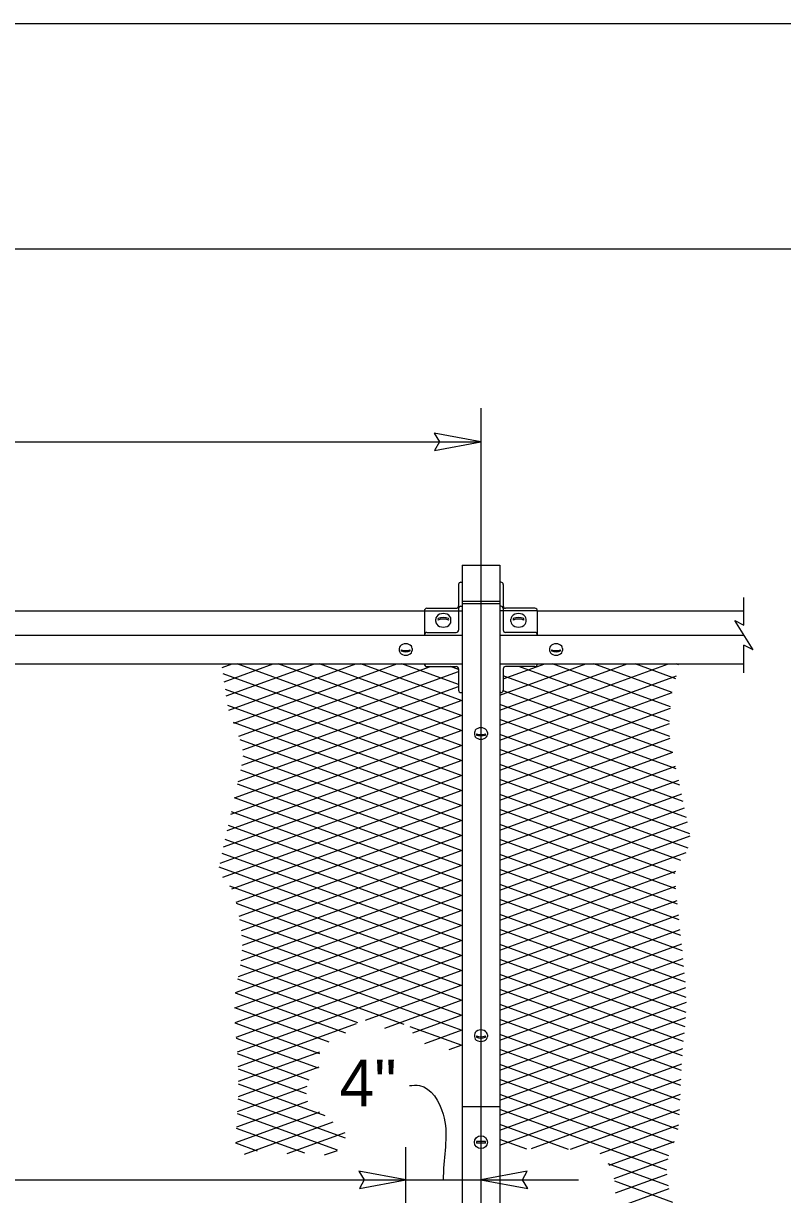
# Model space of a CAD drawing. Extents: x 0 to 2.83, y -0.03 to 1.83.
# Drawn here: x 0.4839 to 0.6943, y 1.5086 to 1.8333 of the extents above; entities that cross this region are included whole.
import ezdxf

# ---------------------------------------------------------------- set-up
doc = ezdxf.new("R2010")
doc.units = 0
for name, color, linetype in [('52', 7, 'Continuous'), ('54', 7, 'Continuous'), ('55', 7, 'Continuous'), ('56', 7, 'Continuous'), ('57', 7, 'Continuous'), ('63', 7, 'Continuous')]:
    doc.layers.add(name, color=color, linetype=linetype)

msp = doc.modelspace()

# ---------------------------------------------------------------- linework, layer by layer
at = {"layer": '52'}
for p, q in [((0.6054476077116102, 1.6831667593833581), (0.6158642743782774, 1.6831667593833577)), ((0.6054476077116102, 1.6831667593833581), (0.6054476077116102, 1.6707794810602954)), ((0.6158642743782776, 1.6831667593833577), (0.6158642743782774, 1.6707794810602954)), ((0.6044710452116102, 1.6777778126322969), (0.6044710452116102, 1.665152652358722)), ((0.6051220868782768, 1.6784288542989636), (0.6054476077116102, 1.6784288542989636)), ((0.6161897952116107, 1.6784288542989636), (0.6158642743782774, 1.6784288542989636)), ((0.6168408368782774, 1.6777778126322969), (0.6168408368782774, 1.665152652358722)), ((0.6054476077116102, 1.6731232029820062), (0.6158642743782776, 1.6731232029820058)), ((0.6158642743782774, 1.6723751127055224), (0.6054476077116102, 1.6723751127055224)), ((0.2096142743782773, 1.670449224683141), (0.6054476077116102, 1.670449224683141)), ((0.5950309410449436, 1.670546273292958), (0.5950309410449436, 1.6637535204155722)), ((0.5950309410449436, 1.670449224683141), (0.6054476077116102, 1.670449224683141)), ((0.5956819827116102, 1.6711973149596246), (0.6038200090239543, 1.6711973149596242)), ((0.6051220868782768, 1.6717331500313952), (0.6054476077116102, 1.6717331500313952)), ((0.6054476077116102, 1.6707794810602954), (0.6054476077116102, 1.5329433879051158)), ((0.6161897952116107, 1.6717331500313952), (0.6158642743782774, 1.6717331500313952)), ((0.6158642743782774, 1.6707794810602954), (0.6158642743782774, 1.5329433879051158)), ((0.626280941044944, 1.670449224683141), (0.6158642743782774, 1.670449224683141)), ((0.6256298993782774, 1.6711973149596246), (0.6174918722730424, 1.6711973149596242)), ((0.626280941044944, 1.670546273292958), (0.626280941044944, 1.6637535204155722)), ((0.626280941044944, 1.670449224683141), (0.68357260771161, 1.670449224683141)), ((0.5981233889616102, 1.6675598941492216), (0.59812338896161, 1.6681390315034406)), ((0.6023551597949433, 1.6675598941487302), (0.6023551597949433, 1.6681390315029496)), ((0.618956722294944, 1.6675598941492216), (0.6189567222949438, 1.6681390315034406)), ((0.6231884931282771, 1.6675598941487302), (0.6231884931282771, 1.6681390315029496)), ((0.1991976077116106, 1.6637535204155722), (0.6054476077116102, 1.6637535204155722)), ((0.5956819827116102, 1.6645016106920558), (0.6038200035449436, 1.6645016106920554)), ((0.6158642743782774, 1.6637535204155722), (0.68357260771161, 1.6637535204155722)), ((0.6256298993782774, 1.6645016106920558), (0.617491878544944, 1.6645016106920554)), ((0.5880322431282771, 1.6600087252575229), (0.5880322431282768, 1.659518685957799)), ((0.5916129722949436, 1.660008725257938), (0.5916129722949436, 1.6595186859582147)), ((0.629698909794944, 1.660008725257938), (0.629698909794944, 1.6595186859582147)), ((0.6332796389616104, 1.6600087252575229), (0.6332796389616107, 1.659518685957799)), ((0.1991976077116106, 1.6557738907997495), (0.6054476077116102, 1.6557738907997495)), ((0.5950309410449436, 1.6557628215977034), (0.5950309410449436, 1.6556768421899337)), ((0.5956819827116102, 1.655025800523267), (0.6038200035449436, 1.655025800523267)), ((0.6044710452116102, 1.6543747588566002), (0.6044710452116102, 1.6484453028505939)), ((0.6158642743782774, 1.6557738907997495), (0.68357260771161, 1.6557738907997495)), ((0.6168408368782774, 1.6543747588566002), (0.6168408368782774, 1.6484453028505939)), ((0.6256298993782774, 1.655025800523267), (0.617491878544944, 1.655025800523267)), ((0.626280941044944, 1.6557628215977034), (0.626280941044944, 1.6556768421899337)), ((0.6051220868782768, 1.6477942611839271), (0.6054476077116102, 1.6477942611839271)), ((0.6161897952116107, 1.6477942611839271), (0.6158642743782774, 1.6477942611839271)), ((0.6088655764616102, 1.636711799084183), (0.6088655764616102, 1.6362217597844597)), ((0.6124463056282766, 1.6367117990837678), (0.6124463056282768, 1.636221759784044)), ((0.6088655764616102, 1.552925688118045), (0.6088655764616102, 1.552435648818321)), ((0.6124463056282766, 1.5529256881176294), (0.6124463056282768, 1.552435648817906)), ((0.6054476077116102, 1.5330983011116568), (0.6158642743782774, 1.5330983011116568)), ((0.6054476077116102, 1.5329433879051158), (0.6054476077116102, 1.1621577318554)), ((0.6158642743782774, 1.5329433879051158), (0.6158642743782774, 1.1621577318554)), ((0.611902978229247, 1.5233909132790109), (0.6094089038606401, 1.5233909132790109)), ((0.611902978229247, 1.5229297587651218), (0.6094089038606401, 1.5229297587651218))]:
    msp.add_line(p, q, dxfattribs=at)
msp.add_circle((0.6106559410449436, 1.5231603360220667), 0.0017903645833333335, dxfattribs=at)
for centre, radius, start, end in [((0.6051220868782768, 1.6777778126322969), 0.0006510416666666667, 90, 180), ((0.6161897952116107, 1.6777778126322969), 0.0006510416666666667, 7.0164775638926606e-15, 90), ((0.5956819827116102, 1.670546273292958), 0.0006510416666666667, 90.00000000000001, 188.57284229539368), ((0.6038200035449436, 1.6718483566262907), 0.0006510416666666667, 270, 0), ((0.6051220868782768, 1.6710821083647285), 0.0006510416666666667, 90, 180), ((0.6161897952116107, 1.6710821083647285), 0.0006510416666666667, 7.0164775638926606e-15, 90), ((0.617491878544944, 1.6718483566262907), 0.0006510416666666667, 180, 270), ((0.6256298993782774, 1.670546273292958), 0.0006510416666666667, 351.4271577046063, 90), ((0.6002392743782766, 1.6645999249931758), 0.004024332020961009, 68.51761783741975, 111.48238216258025), ((0.6002392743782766, 1.66418861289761), 0.004024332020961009, 68.51761783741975, 111.48238216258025), ((0.6210726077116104, 1.6645999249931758), 0.004024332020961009, 68.51761783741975, 111.48238216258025), ((0.6210726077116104, 1.66418861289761), 0.004024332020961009, 68.51761783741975, 111.48238216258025), ((0.5956819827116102, 1.663850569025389), 0.0006510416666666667, 90.00000000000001, 188.57284229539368), ((0.6038200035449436, 1.665152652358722), 0.0006510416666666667, 270, 0), ((0.617491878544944, 1.665152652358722), 0.0006510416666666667, 180, 270), ((0.6256298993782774, 1.663850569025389), 0.0006510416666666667, 351.4271577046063, 90), ((0.5898226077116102, 1.66286134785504), 0.003405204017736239, 248.51761783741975, 291.4823821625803), ((0.5898226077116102, 1.6625133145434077), 0.003405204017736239, 248.51761783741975, 291.4823821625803), ((0.6314892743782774, 1.66286134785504), 0.003405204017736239, 248.51761783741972, 291.4823821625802), ((0.6314892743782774, 1.6625133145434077), 0.003405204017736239, 248.51761783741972, 291.4823821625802), ((0.5956819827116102, 1.6556768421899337), 0.0006510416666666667, 171.42715770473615, 270), ((0.6038200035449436, 1.6543747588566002), 0.0006510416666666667, 0, 89.99999999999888), ((0.617491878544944, 1.6543747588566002), 0.0006510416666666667, 90.00000000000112, 180), ((0.6256298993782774, 1.6556768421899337), 0.0006510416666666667, 270, 8.572842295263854), ((0.6051220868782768, 1.6484453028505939), 0.0006510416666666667, 180, 270), ((0.6161897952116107, 1.6484453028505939), 0.0006510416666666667, 270, 360), ((0.6106559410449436, 1.639564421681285), 0.003405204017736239, 248.51761783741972, 291.4823821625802), ((0.6106559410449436, 1.6392163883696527), 0.003405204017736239, 248.51761783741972, 291.4823821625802), ((0.6106559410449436, 1.5557783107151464), 0.003405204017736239, 248.51761783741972, 291.4823821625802), ((0.6106559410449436, 1.5554302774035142), 0.003405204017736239, 248.51761783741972, 291.4823821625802), ((0.6106559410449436, 1.5231603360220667), 0.0012681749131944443, 169.52431830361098, 190.47568169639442), ((0.6106559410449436, 1.5231603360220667), 0.0012681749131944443, 349.5243183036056, 10.475681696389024)]:
    msp.add_arc(centre, radius, start, end, dxfattribs=at)
for centre, major_axis, ratio, start_param, end_param in [((0.6002392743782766, 1.6681390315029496), (0.002115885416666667, 0), 0.7546999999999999, 0, 3.141592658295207), ((0.6210726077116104, 1.6681390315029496), (0.002115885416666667, 0), 0.7546999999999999, 0, 3.141592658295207), ((0.6002392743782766, 1.6675598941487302), (0.002115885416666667, 0), 0.7546999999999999, 3.141592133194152, 6.283185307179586), ((0.6002392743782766, 1.6681390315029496), (0.001498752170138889, 0), 0.7547, 2.9587575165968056, 3.3244277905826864), ((0.6002392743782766, 1.6681390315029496), (0.001498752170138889, 0), 0.7547, 6.100350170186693, 6.466020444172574), ((0.6210726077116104, 1.6675598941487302), (0.002115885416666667, 0), 0.7546999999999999, 3.141592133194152, 6.283185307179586), ((0.6210726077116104, 1.6681390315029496), (0.001498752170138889, 0), 0.7547, 2.9587575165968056, 3.3244277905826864), ((0.6210726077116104, 1.6681390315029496), (0.001498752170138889, 0), 0.7547, 6.100350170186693, 6.466020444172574), ((0.5898226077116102, 1.6595186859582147), (0.0017903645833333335, 0), 0.7546999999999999, 3.141590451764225, 6.283185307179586), ((0.5898226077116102, 1.660008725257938), (0.0017903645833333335, 0), 0.7546999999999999, 0, 3.1415931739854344), ((0.5898226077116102, 1.6595186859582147), (0.0012681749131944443, 0), 0.7547000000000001, 2.9587575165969, 3.3244277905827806), ((0.5898226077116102, 1.6595186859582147), (0.0012681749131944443, 0), 0.7547000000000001, 6.100350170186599, 6.46602044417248), ((0.6314892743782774, 1.660008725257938), (-0.0017903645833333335, 2.1925642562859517e-19), 0.7546999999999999, 3.141592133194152, 6.283185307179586), ((0.6314892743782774, 1.6595186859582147), (-0.0017903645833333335, 2.1925642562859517e-19), 0.7546999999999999, 1.6226399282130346e-16, 3.141594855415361), ((0.6314892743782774, 1.6595186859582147), (-0.0012681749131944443, 1.5530663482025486e-19), 0.7547000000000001, 6.100350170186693, 6.466020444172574), ((0.6314892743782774, 1.6595186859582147), (-0.0012681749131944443, 1.5530663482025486e-19), 0.7547000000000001, 2.9587575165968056, 3.3244277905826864), ((0.6106559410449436, 1.636711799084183), (-0.0017903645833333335, 2.1925642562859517e-19), 0.7546999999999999, 3.141592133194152, 6.283185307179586), ((0.6106559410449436, 1.6362217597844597), (-0.0017903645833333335, 2.1925642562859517e-19), 0.7546999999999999, 1.6226399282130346e-16, 3.141594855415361), ((0.6106559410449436, 1.6362217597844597), (-0.0012681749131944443, 1.5530663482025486e-19), 0.7547000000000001, 6.100350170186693, 6.466020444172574), ((0.6106559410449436, 1.6362217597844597), (-0.0012681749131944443, 1.5530663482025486e-19), 0.7547000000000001, 2.9587575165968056, 3.3244277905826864), ((0.6106559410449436, 1.552925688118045), (-0.0017903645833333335, 2.1925642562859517e-19), 0.7546999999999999, 3.141592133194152, 6.283185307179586), ((0.6106559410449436, 1.552435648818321), (-0.0017903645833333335, 2.1925642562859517e-19), 0.7546999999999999, 1.6226399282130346e-16, 3.141594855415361), ((0.6106559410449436, 1.552435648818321), (-0.0012681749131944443, 1.5530663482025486e-19), 0.7547000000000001, 6.100350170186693, 6.466020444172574), ((0.6106559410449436, 1.552435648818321), (-0.0012681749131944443, 1.5530663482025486e-19), 0.7547000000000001, 2.9587575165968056, 3.3244277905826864)]:
    msp.add_ellipse(centre, major_axis=major_axis, ratio=ratio, start_param=start_param, end_param=end_param, dxfattribs=at)
at = {"layer": '54'}
for points in [[(0.6106559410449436, 1.717324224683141), (0.5976642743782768, 1.719699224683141), (0.5991726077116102, 1.717324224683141), (0.5978142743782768, 1.714924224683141)], [(0.5898226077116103, 1.5127436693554), (0.5768309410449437, 1.5151186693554), (0.578339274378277, 1.5127436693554), (0.5769809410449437, 1.5103436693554)], [(0.6106559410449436, 1.5127436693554), (0.6236476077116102, 1.5103686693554), (0.6221392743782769, 1.5127436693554), (0.6234976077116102, 1.5151436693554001)]]:
    msp.add_lwpolyline(points, close=True, dxfattribs=at)
at = {"layer": '55'}
for p, q in [((0.1939892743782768, 1.717324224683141), (0.6106559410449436, 1.717324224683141)), ((0.68357260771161, 1.6665491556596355), (0.68357260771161, 1.6741924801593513)), ((0.6860872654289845, 1.659698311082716), (0.6810579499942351, 1.6678087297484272)), ((0.6810579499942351, 1.6678087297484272), (0.68357260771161, 1.6665491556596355)), ((0.6860872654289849, 1.6596983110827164), (0.68357260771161, 1.6609578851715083)), ((0.68357260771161, 1.6533145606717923), (0.68357260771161, 1.6609578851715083)), ((0.5389414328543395, 1.6547772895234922), (0.5416795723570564, 1.6557738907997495)), ((0.6054476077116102, 1.6289121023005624), (0.5391914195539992, 1.6530273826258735)), ((0.5395059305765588, 1.6508258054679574), (0.5531006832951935, 1.6557738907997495)), ((0.5400704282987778, 1.6468743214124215), (0.5645217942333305, 1.6557738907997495)), ((0.5407965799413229, 1.642981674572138), (0.5759429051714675, 1.6557738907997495)), ((0.5421317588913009, 1.6393106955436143), (0.5873640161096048, 1.6557738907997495)), ((0.6054476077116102, 1.6330690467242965), (0.5430665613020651, 1.6557738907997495)), ((0.5435938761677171, 1.6356859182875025), (0.5967297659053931, 1.655025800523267)), ((0.5446224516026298, 1.631903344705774), (0.6044710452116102, 1.6536864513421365)), ((0.6054476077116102, 1.6372259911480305), (0.5544876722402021, 1.6557738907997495)), ((0.6054476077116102, 1.6413829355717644), (0.5659087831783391, 1.6557738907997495)), ((0.6054476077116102, 1.6455398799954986), (0.5773298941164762, 1.6557738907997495)), ((0.6044710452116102, 1.6500522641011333), (0.5887510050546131, 1.6557738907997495)), ((0.6044710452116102, 1.6542092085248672), (0.6022274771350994, 1.655025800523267)), ((0.6158642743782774, 1.6470753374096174), (0.639763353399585, 1.6557738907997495)), ((0.6158642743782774, 1.642918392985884), (0.651184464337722, 1.6557738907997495)), ((0.6158642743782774, 1.6387614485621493), (0.6626055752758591, 1.6557738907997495)), ((0.6168408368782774, 1.6515877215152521), (0.628342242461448, 1.6557738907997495)), ((0.662969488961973, 1.6398149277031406), (0.621177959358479, 1.655025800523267)), ((0.6632341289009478, 1.64387555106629), (0.6305437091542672, 1.6557738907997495)), ((0.6637063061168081, 1.6478606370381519), (0.6419648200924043, 1.6557738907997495)), ((0.6646906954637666, 1.6516592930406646), (0.6533859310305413, 1.6557738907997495)), ((0.665535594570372, 1.655508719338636), (0.6648070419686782, 1.6557738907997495)), ((0.5443695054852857, 1.6276543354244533), (0.6044710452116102, 1.649529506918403)), ((0.6158642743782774, 1.6346045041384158), (0.6649065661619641, 1.6524544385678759)), ((0.6630605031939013, 1.6356248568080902), (0.6168408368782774, 1.652447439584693)), ((0.6054476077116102, 1.6247551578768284), (0.5398178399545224, 1.6486424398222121)), ((0.6158642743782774, 1.6304475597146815), (0.6637063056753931, 1.6478606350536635)), ((0.6638283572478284, 1.6311884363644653), (0.6167912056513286, 1.6483085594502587)), ((0.6054476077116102, 1.6205982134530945), (0.5404777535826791, 1.6442453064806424)), ((0.5433644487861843, 1.6231315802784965), (0.6054476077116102, 1.6457280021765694)), ((0.6647935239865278, 1.626680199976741), (0.6158642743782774, 1.6444889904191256)), ((0.6158642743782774, 1.626290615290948), (0.6632038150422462, 1.6435207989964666)), ((0.5423593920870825, 1.6186088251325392), (0.6054476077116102, 1.6415710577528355)), ((0.6657804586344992, 1.6221640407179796), (0.6158642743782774, 1.640332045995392)), ((0.541354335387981, 1.6140860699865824), (0.6054476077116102, 1.6374141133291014)), ((0.6054476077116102, 1.6164412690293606), (0.5420464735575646, 1.6395173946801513)), ((0.6158642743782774, 1.6221336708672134), (0.6629544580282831, 1.6392730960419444)), ((0.5403492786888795, 1.6095633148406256), (0.6054476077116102, 1.6332571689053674)), ((0.6054476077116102, 1.6122843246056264), (0.5439472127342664, 1.6346686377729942)), ((0.6667430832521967, 1.6176567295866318), (0.6158642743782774, 1.6361751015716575)), ((0.6158642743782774, 1.6179767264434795), (0.6631071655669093, 1.6351717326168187)), ((0.6054476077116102, 1.608127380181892), (0.5447375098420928, 1.6302240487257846)), ((0.6676676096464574, 1.6131632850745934), (0.6158642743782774, 1.6320181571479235)), ((0.6158642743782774, 1.6138197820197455), (0.6638111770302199, 1.631271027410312)), ((0.5393442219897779, 1.6050405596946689), (0.6054476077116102, 1.6291002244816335)), ((0.6685384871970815, 1.6086893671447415), (0.6158642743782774, 1.6278612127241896)), ((0.6158642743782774, 1.6096628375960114), (0.6646339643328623, 1.6274135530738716)), ((0.5383391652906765, 1.6005178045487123), (0.6054476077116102, 1.6249432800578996)), ((0.6054476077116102, 1.6039704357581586), (0.5440707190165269, 1.6263097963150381)), ((0.6681187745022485, 1.6046851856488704), (0.6158642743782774, 1.6237042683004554)), ((0.6158642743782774, 1.6055058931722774), (0.6654752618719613, 1.623562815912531)), ((0.5391164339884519, 1.596643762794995), (0.6054476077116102, 1.620786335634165)), ((0.6054476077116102, 1.599813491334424), (0.5432160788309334, 1.6224639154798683)), ((0.6054476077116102, 1.5956565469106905), (0.54236143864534, 1.618618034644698)), ((0.6158642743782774, 1.601348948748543), (0.6663099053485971, 1.6197096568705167)), ((0.6661118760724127, 1.6012586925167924), (0.6158642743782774, 1.6195473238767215)), ((0.6054476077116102, 1.591499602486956), (0.5415067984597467, 1.6147721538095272)), ((0.541579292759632, 1.5933832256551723), (0.6054476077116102, 1.6166293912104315)), ((0.6158642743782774, 1.5971920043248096), (0.66711959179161, 1.6158474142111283)), ((0.6645221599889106, 1.5976803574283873), (0.6158642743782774, 1.6153903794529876)), ((0.6054476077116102, 1.5873426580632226), (0.540652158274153, 1.6109262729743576)), ((0.542840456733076, 1.5896853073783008), (0.6054476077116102, 1.612472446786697)), ((0.6158642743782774, 1.593035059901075), (0.6679045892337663, 1.6119761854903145)), ((0.6647236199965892, 1.593450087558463), (0.6158642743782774, 1.6112334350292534)), ((0.5436560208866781, 1.5858252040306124), (0.6054476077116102, 1.6083155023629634)), ((0.6158642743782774, 1.5888781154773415), (0.668649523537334, 1.608090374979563)), ((0.6054476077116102, 1.583185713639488), (0.5397975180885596, 1.607080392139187)), ((0.5442713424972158, 1.581892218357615), (0.6054476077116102, 1.604158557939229)), ((0.6651611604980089, 1.589133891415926), (0.6158642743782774, 1.6070764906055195)), ((0.6054476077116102, 1.579028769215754), (0.5389428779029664, 1.6032345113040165)), ((0.6158642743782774, 1.5847211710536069), (0.6675080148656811, 1.6035179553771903)), ((0.6656289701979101, 1.5848066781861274), (0.6158642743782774, 1.6029195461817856)), ((0.6054476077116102, 1.57487182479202), (0.5381365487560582, 1.5993710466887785)), ((0.5445334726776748, 1.5778306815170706), (0.6054476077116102, 1.6000016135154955)), ((0.6660870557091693, 1.5804830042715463), (0.6158642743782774, 1.598762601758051)), ((0.6158642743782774, 1.580564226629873), (0.6646803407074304, 1.5983318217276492)), ((0.5442327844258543, 1.5735642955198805), (0.6054476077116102, 1.595844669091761)), ((0.6664965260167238, 1.5761770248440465), (0.6158642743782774, 1.5946056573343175)), ((0.6054476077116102, 1.570714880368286), (0.5410340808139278, 1.5941594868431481)), ((0.5434392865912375, 1.5691185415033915), (0.6054476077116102, 1.5916877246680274)), ((0.6158642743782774, 1.576407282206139), (0.6646564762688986, 1.5941661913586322)), ((0.6054476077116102, 1.566557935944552), (0.5429245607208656, 1.58931446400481)), ((0.666894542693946, 1.571875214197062), (0.6158642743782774, 1.590448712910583)), ((0.6158642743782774, 1.572250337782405), (0.665053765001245, 1.590153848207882)), ((0.5426682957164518, 1.5646809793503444), (0.6054476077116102, 1.587530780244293)), ((0.6054476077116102, 1.5624009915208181), (0.5438386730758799, 1.584824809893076)), ((0.6673175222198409, 1.5675643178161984), (0.6158642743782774, 1.5862917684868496)), ((0.6158642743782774, 1.568093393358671), (0.6654826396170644, 1.586153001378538)), ((0.5424236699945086, 1.560434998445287), (0.6054476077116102, 1.583373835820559)), ((0.6158642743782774, 1.563936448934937), (0.6659136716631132, 1.582152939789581)), ((0.6675872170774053, 1.5633092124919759), (0.6158642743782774, 1.582134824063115)), ((0.5425795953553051, 1.55633480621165), (0.6054476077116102, 1.579216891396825)), ((0.6054476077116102, 1.558244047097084), (0.5444139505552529, 1.5804584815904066)), ((0.6158642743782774, 1.559779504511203), (0.6663176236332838, 1.578143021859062)), ((0.5428522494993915, 1.552277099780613), (0.6054476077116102, 1.575059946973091)), ((0.6054476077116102, 1.55408710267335), (0.544502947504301, 1.5762691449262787)), ((0.6675532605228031, 1.559164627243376), (0.6158642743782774, 1.5779778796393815)), ((0.5894152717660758, 1.5557654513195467), (0.5440327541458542, 1.5722833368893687)), ((0.6158642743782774, 1.555622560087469), (0.6666743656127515, 1.5741159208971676)), ((0.6672357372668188, 1.555123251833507), (0.6158642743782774, 1.5738209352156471)), ((0.5431537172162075, 1.548229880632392), (0.6054476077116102, 1.570903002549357)), ((0.576567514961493, 1.5562847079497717), (0.5432980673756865, 1.5683937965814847)), ((0.6158642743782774, 1.551465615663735), (0.6670745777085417, 1.5701046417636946)), ((0.6668275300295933, 1.551114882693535), (0.6158642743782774, 1.569663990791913)), ((0.5786973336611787, 1.5570097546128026), (0.6054476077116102, 1.566746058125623)), ((0.6158642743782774, 1.5473086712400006), (0.6674374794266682, 1.5660797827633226)), ((0.6665025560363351, 1.5470762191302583), (0.6158642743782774, 1.565507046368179)), ((0.5731766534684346, 1.55336193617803), (0.5426416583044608, 1.564475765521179)), ((0.5839844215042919, 1.5547771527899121), (0.6054476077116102, 1.562589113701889)), ((0.6158642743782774, 1.543151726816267), (0.6676158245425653, 1.561987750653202)), ((0.5685814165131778, 1.5508775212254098), (0.5424242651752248, 1.5603979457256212)), ((0.6662702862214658, 1.5430038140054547), (0.6158642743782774, 1.5613501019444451)), ((0.5659991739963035, 1.5476604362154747), (0.5425883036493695, 1.556181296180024)), ((0.5433972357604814, 1.5441615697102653), (0.5761573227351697, 1.556085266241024)), ((0.5918236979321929, 1.5534734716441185), (0.6054476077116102, 1.558432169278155)), ((0.6158642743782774, 1.5389947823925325), (0.6674669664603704, 1.557776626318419)), ((0.6660725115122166, 1.5389188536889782), (0.6158642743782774, 1.557193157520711)), ((0.6054476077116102, 1.549930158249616), (0.5910554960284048, 1.5551684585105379)), ((0.5950952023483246, 1.5505072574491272), (0.6054476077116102, 1.554275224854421)), ((0.6158642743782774, 1.534837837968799), (0.6670688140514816, 1.553474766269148)), ((0.6658830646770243, 1.5348308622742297), (0.6158642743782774, 1.553036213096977)), ((0.5656185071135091, 1.5436420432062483), (0.542879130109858, 1.5519184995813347)), ((0.6018718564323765, 1.5488168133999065), (0.6054476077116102, 1.550118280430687)), ((0.6158642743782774, 1.5306808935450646), (0.66664878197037, 1.5491649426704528)), ((0.6656750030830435, 1.5307496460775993), (0.6158642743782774, 1.548879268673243)), ((0.5630903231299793, 1.540405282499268), (0.5431944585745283, 1.547646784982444)), ((0.5434949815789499, 1.5400402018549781), (0.5660035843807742, 1.548232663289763)), ((0.5434207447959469, 1.5358562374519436), (0.5658335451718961, 1.5440138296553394)), ((0.5622812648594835, 1.5365428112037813), (0.5434285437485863, 1.5434046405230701)), ((0.6158642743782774, 1.526523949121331), (0.6663727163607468, 1.5449075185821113)), ((0.6653367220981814, 1.5267158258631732), (0.6158642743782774, 1.5447223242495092)), ((0.5675335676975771, 1.5304741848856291), (0.5434917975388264, 1.539224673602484)), ((0.6158642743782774, 1.5223670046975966), (0.666154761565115, 1.5406712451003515)), ((0.6641286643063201, 1.5229985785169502), (0.6158642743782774, 1.540565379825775)), ((0.5432248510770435, 1.5316279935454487), (0.5625414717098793, 1.5386586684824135)), ((0.6627517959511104, 1.5193427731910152), (0.6158642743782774, 1.536408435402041)), ((0.6247071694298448, 1.5214286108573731), (0.6659584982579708, 1.5364428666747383)), ((0.5429652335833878, 1.5273765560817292), (0.5627051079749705, 1.5345612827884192)), ((0.5731121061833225, 1.524286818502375), (0.5433925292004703, 1.5351038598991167)), ((0.5427027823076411, 1.523124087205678), (0.5660327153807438, 1.5316154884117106)), ((0.5709002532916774, 1.5209349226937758), (0.5431899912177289, 1.5310206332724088)), ((0.6622157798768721, 1.5153809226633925), (0.6158642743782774, 1.5322514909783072)), ((0.6355132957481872, 1.521204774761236), (0.6657535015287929, 1.532211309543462)), ((0.5618246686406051, 1.520081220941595), (0.542938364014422, 1.52695527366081)), ((0.5451073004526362, 1.5198423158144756), (0.5696918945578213, 1.528790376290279)), ((0.6349790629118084, 1.5211373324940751), (0.6158642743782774, 1.5280945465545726)), ((0.6436918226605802, 1.5200245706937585), (0.6655082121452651, 1.5279650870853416)), ((0.5487347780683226, 1.520688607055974), (0.5426892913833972, 1.5228889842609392)), ((0.5569255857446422, 1.5199868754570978), (0.5730532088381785, 1.525856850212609)), ((0.6233518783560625, 1.5212123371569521), (0.6158642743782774, 1.523937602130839)), ((0.6461702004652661, 1.5167696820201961), (0.6642738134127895, 1.5233588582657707)), ((0.567332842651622, 1.5196178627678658), (0.5708702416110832, 1.520905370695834)), ((0.5898226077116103, 1.4624507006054), (0.5898226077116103, 1.5217898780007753)), ((0.6626813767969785, 1.5110545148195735), (0.6459727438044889, 1.517135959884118)), ((0.6475827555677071, 1.5131268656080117), (0.6625510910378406, 1.5185748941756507)), ((0.6479868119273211, 1.5091169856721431), (0.662253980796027, 1.5143098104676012)), ((0.2148226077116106, 1.5127436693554), (0.5898226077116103, 1.5127436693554)), ((0.5898226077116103, 1.5127436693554), (0.6106559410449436, 1.5127436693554)), ((0.6106559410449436, 1.5127436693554), (0.6376830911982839, 1.5127436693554)), ((0.6158642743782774, 1.4932683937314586), (0.6628249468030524, 1.5103606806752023)), ((0.6638401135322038, 1.5064758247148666), (0.6477713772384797, 1.5123243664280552))]:
    msp.add_line(p, q, dxfattribs=at)
msp.add_spline([(0.5908238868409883, 1.5388461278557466), (0.5936339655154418, 1.5388640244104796), (0.6001888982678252, 1.530900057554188), (0.6002598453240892, 1.515007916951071), (0.6002392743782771, 1.5127436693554)], degree=3, dxfattribs=at)
at = {"layer": '56'}
msp.add_line((0.6106559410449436, 1.7266594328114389), (0.6106559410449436, 1.0713374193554), dxfattribs=at)
at = {"layer": '63'}
msp.add_line((0, 1.8333333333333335), (2.833333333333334, 1.8333333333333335), dxfattribs=at)
msp.add_lwpolyline([(2.729175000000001, 1.770775), (0.10417500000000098, 1.770775), (0.10417500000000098, 0.06244166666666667), (2.729175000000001, 0.06244166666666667)], close=True, dxfattribs=at)

# ---------------------------------------------------------------- texts
at = {"layer": '57'}
msp.add_text('4"', height=0.012980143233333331, dxfattribs=at).set_placement((0.5714598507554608, 1.5330992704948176))

doc.saveas('drawing.dxf')
